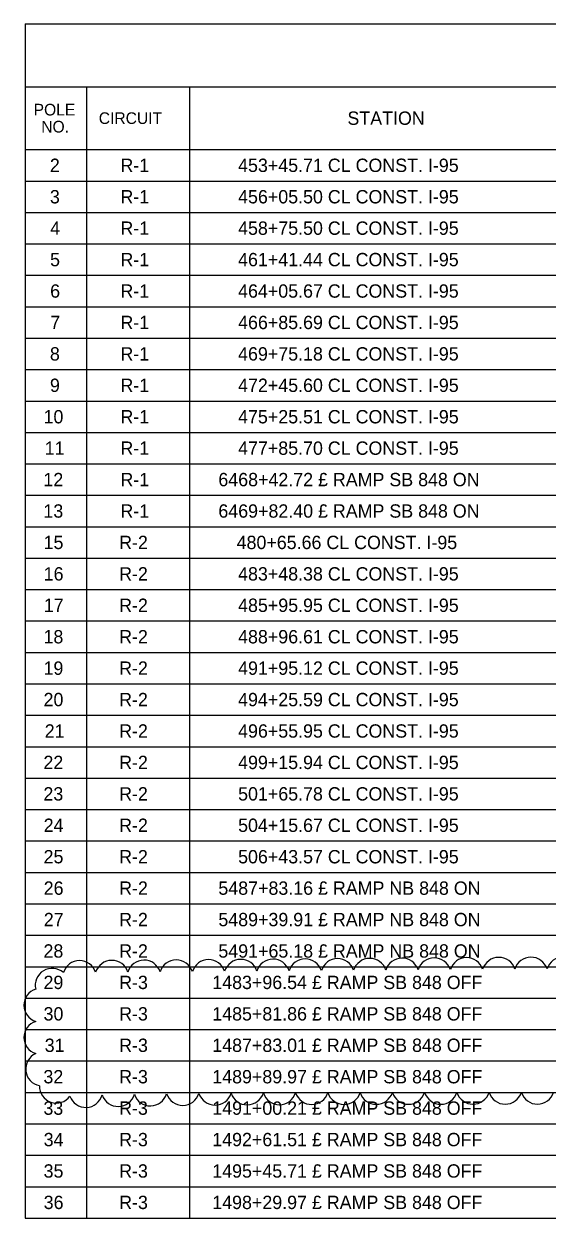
# Model space of a CAD drawing. Extents: x -816.7 to -800.7, y -2197.9 to -2187.9.
# Drawn here: x -815.97 to -813.23, y -2194.13 to -2187.86 of the extents above; entities that cross this region are included whole.
import ezdxf

# ---------------------------------------------------------------- set-up
doc = ezdxf.new("R2010")
doc.units = 0
for name, color, linetype in [('ScratchEle_dp', 7, 'Continuous'), ('SumBoxBorder_dp', 7, 'Continuous'), ('SumBoxLines_dp', 7, 'Continuous'), ('SumBoxLinesMin_dp', 7, 'Continuous'), ('TextLabel', 7, 'Continuous')]:
    doc.layers.add(name, color=color, linetype=linetype)

msp = doc.modelspace()

# ---------------------------------------------------------------- linework, layer by layer
at = {"layer": 'ScratchEle_dp'}
for centre, start, end in [((-815.6819, -2192.8631), 17.94937, 162.94937), ((-815.5126, -2192.8617), 17.94937, 162.94937), ((-815.3433, -2192.8604), 17.94937, 162.94937), ((-815.1741, -2192.8591), 17.94937, 162.94937), ((-815.0048, -2192.8577), 17.94937, 162.94937), ((-814.8355, -2192.8564), 17.94937, 162.94937), ((-814.6663, -2192.8551), 17.94937, 162.94937), ((-814.497, -2192.8538), 17.94937, 162.94937), ((-814.3277, -2192.8524), 17.94937, 162.94937), ((-814.1585, -2192.8511), 17.94937, 162.94937), ((-813.9892, -2192.8498), 17.94937, 162.94937), ((-813.8199, -2192.8485), 17.94104, 162.94104), ((-813.6507, -2192.8472), 17.91499, 162.91499), ((-813.4814, -2192.846), 17.8851, 162.8851), ((-813.3122, -2192.8449), 17.8509, 162.8509), ((-813.1429, -2192.844), 17.81126, 162.81126), ((-815.8256, -2192.9035), 48.4646, 193.4646), ((-815.8852, -2193.0088), 107.5, 252.5), ((-815.8852, -2193.178), 107.5, 252.5), ((-815.8756, -2193.3437), 114.144, 259.144), ((-815.8036, -2193.4334), 178.34348, 323.34348), ((-815.6489, -2193.4564), 199.71315, 344.71315), ((-815.4792, -2193.4513), 198.75276, 343.75276), ((-815.3098, -2193.4482), 198.36843, 343.36843), ((-815.1404, -2193.4459), 198.14491, 343.14491), ((-814.9711, -2193.4442), 197.99402, 342.99402), ((-814.8018, -2193.4429), 197.8833, 342.8833), ((-814.6325, -2193.4419), 197.79757, 342.79757), ((-814.4632, -2193.4412), 197.72865, 342.72865), ((-814.2939, -2193.4406), 197.67166, 342.67166), ((-814.1246, -2193.4401), 197.62352, 342.62352), ((-813.9553, -2193.4398), 197.58216, 342.58216), ((-813.786, -2193.4396), 197.5461, 342.5461), ((-813.6167, -2193.4395), 197.51433, 342.51433), ((-813.4474, -2193.4395), 197.52177, 342.52177), ((-813.2782, -2193.4394), 197.56792, 342.56792)]:
    msp.add_arc(centre, 0.0887, start, end, dxfattribs=at)
at = {"layer": 'SumBoxBorder_dp'}
for p, q in [((-815.9673, -2187.8562), (-808.5423, -2187.8562)), ((-815.9673, -2187.8562), (-815.9673, -2194.1262)), ((-815.9673, -2188.1862), (-808.5423, -2188.1862)), ((-815.9673, -2188.1862), (-808.5423, -2188.1862)), ((-815.9673, -2194.1262), (-808.5423, -2194.1262))]:
    msp.add_line(p, q, dxfattribs=at)
at = {"layer": 'SumBoxLines_dp'}
for p, q in [((-815.6448, -2188.1862), (-815.6448, -2194.1262)), ((-815.6448, -2188.1862), (-815.6448, -2194.1262)), ((-815.1048, -2188.1862), (-815.1048, -2194.1262)), ((-815.1048, -2188.1862), (-815.1048, -2194.1262)), ((-815.9673, -2188.5162), (-808.5423, -2188.5162))]:
    msp.add_line(p, q, dxfattribs=at)
at = {"layer": 'SumBoxLinesMin_dp'}
for p, q in [((-815.9673, -2188.5162), (-808.5423, -2188.5162)), ((-815.9673, -2188.6812), (-808.5423, -2188.6812)), ((-815.9673, -2188.6812), (-808.5423, -2188.6812)), ((-815.9673, -2188.8462), (-808.5423, -2188.8462)), ((-815.9673, -2188.8462), (-808.5423, -2188.8462)), ((-815.9673, -2189.0112), (-808.5423, -2189.0112)), ((-815.9673, -2189.0112), (-808.5423, -2189.0112)), ((-815.9673, -2189.1762), (-808.5423, -2189.1762)), ((-815.9673, -2189.1762), (-808.5423, -2189.1762)), ((-815.9673, -2189.3412), (-808.5423, -2189.3412)), ((-815.9673, -2189.3412), (-808.5423, -2189.3412)), ((-815.9673, -2189.5062), (-808.5423, -2189.5062)), ((-815.9673, -2189.5062), (-808.5423, -2189.5062)), ((-815.9673, -2189.6712), (-808.5423, -2189.6712)), ((-815.9673, -2189.6712), (-808.5423, -2189.6712)), ((-815.9673, -2189.8362), (-808.5423, -2189.8362)), ((-815.9673, -2189.8362), (-808.5423, -2189.8362)), ((-815.9673, -2190.0012), (-808.5423, -2190.0012)), ((-815.9673, -2190.0012), (-808.5423, -2190.0012)), ((-815.9673, -2190.1662), (-808.5423, -2190.1662)), ((-815.9673, -2190.1662), (-808.5423, -2190.1662)), ((-815.9673, -2190.3312), (-808.5423, -2190.3312)), ((-815.9673, -2190.3312), (-808.5423, -2190.3312)), ((-815.9673, -2190.4962), (-808.5423, -2190.4962)), ((-815.9673, -2190.4962), (-808.5423, -2190.4962)), ((-815.9673, -2190.6612), (-808.5423, -2190.6612)), ((-815.9673, -2190.6612), (-808.5423, -2190.6612)), ((-815.9673, -2190.8262), (-808.5423, -2190.8262)), ((-815.9673, -2190.8262), (-808.5423, -2190.8262)), ((-815.9673, -2190.9912), (-808.5423, -2190.9912)), ((-815.9673, -2190.9912), (-808.5423, -2190.9912)), ((-815.9673, -2191.1562), (-808.5423, -2191.1562)), ((-815.9673, -2191.1562), (-808.5423, -2191.1562)), ((-815.9673, -2191.3212), (-808.5423, -2191.3212)), ((-815.9673, -2191.3212), (-808.5423, -2191.3212)), ((-815.9673, -2191.4862), (-808.5423, -2191.4862)), ((-815.9673, -2191.4862), (-808.5423, -2191.4862)), ((-815.9673, -2191.6512), (-808.5423, -2191.6512)), ((-815.9673, -2191.6512), (-808.5423, -2191.6512)), ((-815.9673, -2191.8162), (-808.5423, -2191.8162)), ((-815.9673, -2191.8162), (-808.5423, -2191.8162)), ((-815.9673, -2191.9812), (-808.5423, -2191.9812)), ((-815.9673, -2191.9812), (-808.5423, -2191.9812)), ((-815.9673, -2192.1462), (-808.5423, -2192.1462)), ((-815.9673, -2192.1462), (-808.5423, -2192.1462)), ((-815.9673, -2192.3112), (-808.5423, -2192.3112)), ((-815.9673, -2192.3112), (-808.5423, -2192.3112)), ((-815.9673, -2192.4762), (-809.8248, -2192.4762)), ((-815.9673, -2192.4762), (-808.5423, -2192.4762)), ((-815.9673, -2192.6412), (-808.5423, -2192.6412)), ((-815.9673, -2192.6412), (-808.5423, -2192.6412)), ((-815.9673, -2192.8062), (-808.5423, -2192.8062)), ((-815.9673, -2192.8062), (-808.5423, -2192.8062)), ((-815.9673, -2192.9712), (-808.5423, -2192.9712)), ((-815.9673, -2192.9712), (-808.5423, -2192.9712)), ((-815.9673, -2193.1362), (-808.5423, -2193.1362)), ((-815.9673, -2193.1362), (-808.5423, -2193.1362)), ((-815.9673, -2193.3012), (-808.5423, -2193.3012)), ((-815.9673, -2193.3012), (-808.5423, -2193.3012)), ((-815.9673, -2193.4662), (-808.5423, -2193.4662)), ((-815.9673, -2193.4662), (-808.5423, -2193.4662)), ((-815.9673, -2193.6312), (-808.5423, -2193.6312)), ((-815.9673, -2193.6312), (-808.5423, -2193.6312)), ((-815.9673, -2193.7962), (-808.5423, -2193.7962)), ((-815.9673, -2193.7962), (-808.5423, -2193.7962)), ((-815.9673, -2193.9612), (-808.5423, -2193.9612)), ((-815.9673, -2193.9612), (-808.5423, -2193.9612))]:
    msp.add_line(p, q, dxfattribs=at)

# ---------------------------------------------------------------- texts
at = {"layer": 'TextLabel'}
for s, height, p in [('POLE', 0.06125, (-815.9227, -2188.3372)), ('CIRCUIT', 0.06125, (-815.5808, -2188.3818)), ('STATION', 0.07, (-814.2757, -2188.3862)), ('NO.', 0.06125, (-815.8828, -2188.4265)), ('2', 0.07, (-815.8375, -2188.6337)), ('R-1', 0.07, (-815.4673, -2188.6337)), ('453+45.71 CL CONST. I-95', 0.07, (-814.8496, -2188.6337)), ('3', 0.07, (-815.8375, -2188.7987)), ('R-1', 0.07, (-815.4673, -2188.7987)), ('456+05.50 CL CONST. I-95', 0.07, (-814.8496, -2188.7987)), ('4', 0.07, (-815.8361, -2188.9637)), ('R-1', 0.07, (-815.4673, -2188.9637)), ('458+75.50 CL CONST. I-95', 0.07, (-814.8496, -2188.9637)), ('5', 0.07, (-815.8366, -2189.1287)), ('R-1', 0.07, (-815.4673, -2189.1287)), ('461+41.44 CL CONST. I-95', 0.07, (-814.8496, -2189.1287)), ('6', 0.07, (-815.8361, -2189.2937)), ('R-1', 0.07, (-815.4673, -2189.2937)), ('464+05.67 CL CONST. I-95', 0.07, (-814.8496, -2189.2937)), ('7', 0.07, (-815.8355, -2189.4587)), ('R-1', 0.07, (-815.4673, -2189.4587)), ('466+85.69 CL CONST. I-95', 0.07, (-814.8496, -2189.4587)), ('8', 0.07, (-815.8373, -2189.6237)), ('R-1', 0.07, (-815.4673, -2189.6237)), ('469+75.18 CL CONST. I-95', 0.07, (-814.8496, -2189.6237)), ('9', 0.07, (-815.8371, -2189.7887)), ('R-1', 0.07, (-815.4673, -2189.7887)), ('472+45.60 CL CONST. I-95', 0.07, (-814.8496, -2189.7887)), ('10', 0.07, (-815.8708, -2189.9537)), ('R-1', 0.07, (-815.4673, -2189.9537)), ('475+25.51 CL CONST. I-95', 0.07, (-814.8496, -2189.9537)), ('477+85.70 CL CONST. I-95', 0.07, (-814.8496, -2190.1187)), ('11', 0.07, (-815.8646, -2190.1187)), ('R-1', 0.07, (-815.4673, -2190.1187)), ('12', 0.07, (-815.8714, -2190.2837)), ('R-1', 0.07, (-815.4673, -2190.2837)), ('6468+42.72 £ RAMP SB 848 ON', 0.07, (-814.9532, -2190.2837)), ('13', 0.07, (-815.8714, -2190.4487)), ('R-1', 0.07, (-815.4673, -2190.4487)), ('6469+82.40 £ RAMP SB 848 ON', 0.07, (-814.9532, -2190.4487)), ('15', 0.07, (-815.8705, -2190.6137)), ('R-2', 0.07, (-815.474, -2190.6137)), (' 480+65.66 CL CONST. I-95', 0.07, (-814.8834, -2190.6137)), ('16', 0.07, (-815.87, -2190.7787)), ('R-2', 0.07, (-815.474, -2190.7787)), ('483+48.38 CL CONST. I-95', 0.07, (-814.8496, -2190.7787)), ('17', 0.07, (-815.8694, -2190.9437)), ('R-2', 0.07, (-815.474, -2190.9437)), ('485+95.95 CL CONST. I-95', 0.07, (-814.8496, -2190.9437)), ('18', 0.07, (-815.8711, -2191.1087)), ('R-2', 0.07, (-815.474, -2191.1087)), ('488+96.61 CL CONST. I-95', 0.07, (-814.8496, -2191.1087)), ('19', 0.07, (-815.871, -2191.2737)), ('R-2', 0.07, (-815.474, -2191.2737)), ('491+95.12 CL CONST. I-95', 0.07, (-814.8496, -2191.2737)), ('20', 0.07, (-815.8708, -2191.4387)), ('R-2', 0.07, (-815.474, -2191.4387)), ('494+25.59 CL CONST. I-95', 0.07, (-814.8496, -2191.4387)), ('21', 0.07, (-815.8646, -2191.6037)), ('R-2', 0.07, (-815.474, -2191.6037)), ('496+55.95 CL CONST. I-95', 0.07, (-814.8496, -2191.6037)), ('22', 0.07, (-815.8714, -2191.7687)), ('R-2', 0.07, (-815.474, -2191.7687)), ('499+15.94 CL CONST. I-95', 0.07, (-814.8496, -2191.7687)), ('23', 0.07, (-815.8714, -2191.9337)), ('R-2', 0.07, (-815.474, -2191.9337)), ('501+65.78 CL CONST. I-95', 0.07, (-814.8496, -2191.9337)), ('24', 0.07, (-815.87, -2192.0987)), ('R-2', 0.07, (-815.474, -2192.0987)), ('504+15.67 CL CONST. I-95', 0.07, (-814.8496, -2192.0987)), ('25', 0.07, (-815.8705, -2192.2637)), ('R-2', 0.07, (-815.474, -2192.2637)), ('506+43.57 CL CONST. I-95', 0.07, (-814.8496, -2192.2637)), ('26', 0.07, (-815.87, -2192.4287)), ('R-2', 0.07, (-815.474, -2192.4287)), ('5487+83.16 £ RAMP NB 848 ON', 0.07, (-814.9532, -2192.4287)), ('27', 0.07, (-815.8694, -2192.5937)), ('R-2', 0.07, (-815.474, -2192.5937)), ('5489+39.91 £ RAMP NB 848 ON', 0.07, (-814.9532, -2192.5937)), ('28', 0.07, (-815.8711, -2192.7587)), ('R-2', 0.07, (-815.474, -2192.7587)), ('5491+65.18 £ RAMP NB 848 ON', 0.07, (-814.9532, -2192.7587)), ('29', 0.07, (-815.871, -2192.9237)), ('R-3', 0.07, (-815.474, -2192.9237)), ('1483+96.54 £ RAMP SB 848 OFF', 0.07, (-814.9852, -2192.9237)), ('30', 0.07, (-815.8708, -2193.0887)), ('R-3', 0.07, (-815.474, -2193.0887)), ('1485+81.86 £ RAMP SB 848 OFF', 0.07, (-814.9852, -2193.0887)), ('31', 0.07, (-815.8646, -2193.2537)), ('R-3', 0.07, (-815.474, -2193.2537)), ('1487+83.01 £ RAMP SB 848 OFF', 0.07, (-814.9852, -2193.2537)), ('32', 0.07, (-815.8714, -2193.4187)), ('R-3', 0.07, (-815.474, -2193.4187)), ('1489+89.97 £ RAMP SB 848 OFF', 0.07, (-814.9852, -2193.4187)), ('33', 0.07, (-815.8714, -2193.5837)), ('R-3', 0.07, (-815.474, -2193.5837)), ('1491+00.21 £ RAMP SB 848 OFF', 0.07, (-814.9852, -2193.5837)), ('34', 0.07, (-815.87, -2193.7487)), ('R-3', 0.07, (-815.474, -2193.7487)), ('1492+61.51 £ RAMP SB 848 OFF', 0.07, (-814.9852, -2193.7487)), ('35', 0.07, (-815.8705, -2193.9137)), ('R-3', 0.07, (-815.474, -2193.9137)), ('1495+45.71 £ RAMP SB 848 OFF', 0.07, (-814.9852, -2193.9137)), ('36', 0.07, (-815.87, -2194.0787)), ('R-3', 0.07, (-815.474, -2194.0787)), ('1498+29.97 £ RAMP SB 848 OFF', 0.07, (-814.9852, -2194.0787))]:
    msp.add_text(s, height=height, dxfattribs=at).set_placement(p)

doc.saveas('drawing.dxf')
